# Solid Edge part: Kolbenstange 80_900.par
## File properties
Username: ahadarics
Dokumentum tartalom típus: 0
Author: ahadarics
Last saved by: ahadarics
Revision: 100
Sűrűség: 0,000 kg/m^3
Pontosság: 0,990
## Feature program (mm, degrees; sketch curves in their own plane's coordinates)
base feature "unnamed BaseFeature 1"
thread "unnamed Thread 1"
chamfer "Letörés_1"  SetBackValue2 = 20 deg
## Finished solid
Body 1: solid body, 19 faces, 27 edges, 11 vertices.
  Faces by surface: plane 8, cylinder 5, cone 3, torus 3
  Edges by curve: circle 15, line 7, curve on surface 3, ellipse 2
Bounding box of the edges (mm; curved faces can reach further): 80.000 x 80.000 x 1074.000, from (-40, -40, -79.5) to (40, 40, 994.5).
Cylindrical faces by radius (mm): R8.75 x1, R10 x1, R12.25 x1, R12.5 x1, R40 x1
Conical faces (half-angle, radius in mm at the cone's reference point): 20 deg R10 x1, 30 deg R12.375 x1, 60 deg R9.375 x1
Toroidal faces (ring radius, tube radius in mm): R9.15 r0.4 x2, R10.45 r1.8 x1
Planar faces by outward normal: +x 1, +z 3, -x 1, -z 1, oblique 2
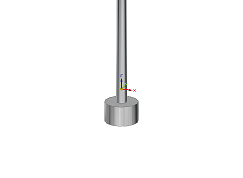
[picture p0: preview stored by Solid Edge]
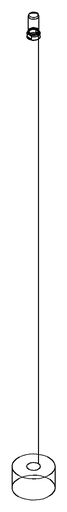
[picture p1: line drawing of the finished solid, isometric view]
